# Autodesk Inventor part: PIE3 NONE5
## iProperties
Shininess: 64.0
Length Units: 11269
Angle Units: 11279
Time Units: 11290
Mass Units: 11286
Length Display Precision: 3
Angle Display Precision: 2
Compacted: True
Part Number: PIE3 NONE5
Document SubType Name: Modeling
Created: 2004-08
Designer: John Blackburn
Manufacturer: Standard
Standards Organization: Custom
Density: 0.0
Volumn: 0.0
Area: 0.0
PropertySet Name: Model Information
Control State: 0
Master: False
Checked Out: False
Author: John Blackburn
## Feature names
1. Erst1
